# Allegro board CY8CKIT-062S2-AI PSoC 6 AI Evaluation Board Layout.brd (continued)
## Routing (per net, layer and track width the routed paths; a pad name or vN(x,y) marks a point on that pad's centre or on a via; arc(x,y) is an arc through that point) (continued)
VCC_3V3: length 116.3
  TOP w0.229: v1(29.54,39.71) 29.54,40.03 R81.1 ; v1(6.23,19.3) 6.23,19.35 6.09,19.5 C66.1 6.09,20.28 5.85,20.53 U3.8 ; U19.B2 U19.B3 17.89,21.54 17.05,21.54 C115.1 16.22,21.56 15.34,20.68 15.34,20.31 15.57,20.08 v1(15.57,18.62) ; U18.5 10.39,20.14 C116.2 v1(9.94,20.12) ; v1(16.47,13.86) C81.1 17.08,14.44 17.11,14.41 FB10.1 ; v1(5.18,40.07) 5.18,40.83 R73.1 ; R285.2 13.67,21.82 12.68,20.83 v1(12.68,20.3) 12.57,20.18 12.27,20.18 C121.1 12.21,20.8 12.15,20.85 U18.8 ; U3.6 7.15,20.58 7.35,20.37 7.35,19.87 C67.1 v1(7.34,19.32)
  L03_SIG1 w0.229: v1(7.44,44.53) 6.64,44.53 5.44,43.33 5.44,40.34 v1(5.18,40.07) 4.97,39.86 4.97,39.14 5.27,38.84 5.27,37.29 v1(5.44,37.11) ; v1(7.34,19.32) 7.34,20.67 8.14,21.46 v1(8.14,21.64)
  L04_SIG2 w0.229: v1(29.54,39.71) 29.62,39.64 29.62,39.07 29.11,38.56 28.3,38.56 28.02,38.84 26.76,38.84 26.44,38.52 26.44,37.52 26.21,37.29 25.51,37.29 24.98,37.82 19.02,37.82 v1(18.59,37.39) 17.2,37.39 16.2,38.39 6.04,38.39 5.67,38.02 5.67,37.34 v1(5.44,37.11) ; v1(13.38,43.59) 8.34,43.59 7.44,44.49 v1(7.44,44.53) ; v1(9.94,20.12) 10.37,20.55 12.01,20.55 12.26,20.3 v1(12.68,20.3) ; 7.34,19.26 7.34,19.26 6.96,18.89 6.62,18.89 6.23,19.27 v1(6.23,19.3) 4.53,19.3 v1(4.1,19.74) ; 7.34,19.26 8.1,18.51 15.41,18.51 15.52,18.62 v1(15.57,18.62) ; 7.34,19.26 v1(7.34,19.32)
  BOTTOM w0.229: TP10.1 R39.1 13.21,18.39 13.21,19.76 12.68,20.29 v1(12.68,20.3) ; U4.2 5.44,44.02 5.67,44.25 6.71,44.25 6.9,44.06 C68.1 v1(7.44,44.53) ; v1(5.44,37.11) 5.44,36.8 3.74,35.1 3.74,32.94 J17.5 3.03,29.85 3.03,27.06 3.54,26.54 3.54,20.29 v1(4.1,19.74) ; v1(18.59,37.39) 18.57,37.42 J16.2 ; U5.2 29.31,41.16 29.71,40.76 C71.1 29.5,40.1 29.5,39.76 v1(29.54,39.71) ; v1(13.38,43.59) J15.1 ; v1(8.14,21.64) 7.98,21.8 R286.2
  BOTTOM w0.381: v1(15.57,18.62) 15.57,17.58 15.34,17.35 13.46,17.35 13.18,17.63 R39.1
  vias: v1(18.73,14.3) v1(19.26,14.3)
VCC_3V6: length 9.4
  TOP w0.229: R26.1 v1(27.71,11.16)
  TOP w0.381: v1(29,32.14) 28.66,32.14 28.26,31.74 R96.1
  L03_SIG1 w0.229: v1(10.77,16.52) 10.77,16.49 11.52,15.75 11.69,15.75 12.04,15.4 12.89,15.4 12.9,15.41 v1(14.12,15.41)
  BOTTOM w0.229: v1(10.77,16.52) C253.1 11.1,15.89 11.38,15.61 11.38,14.57 11.27,14.46 R21.1 ; v1(23.96,12.55) 23.74,12.33 R25.1 ; R19.1 v1(20.63,12.74)
  vias: v1(14.12,14.83) v1(18.5,9.96) v1(18.48,9.37) v1(21.29,10.06) v1(21.29,9.53) v1(30.11,12.7) v1(30.59,12.37)
VCCD: length 17
  TOP w0.229: U1.A2 v1(6.79,26.08)
  L04_SIG2 w0.229: v1(4.84,24.46) 4.25,23.88 4.25,22.67 5.76,21.16 8.34,21.16 8.78,21.59 v1(12.84,21.59)
  BOTTOM w0.229: v1(12.84,21.59) 12.84,21 R40.2 12.71,20.73 12.5,20.73 12.48,20.71 TP12.1 ; v1(4.84,24.46) 5.29,24.92 5.29,25.44 5.58,25.73 6.09,25.73 6.29,25.93 C39.1 6.71,26.16 v1(6.79,26.08)
VDD_NS: length 3.5
  TOP w0.229: U1.J1 v1(12.64,25.43)
  BOTTOM w0.229: FB3.1 12.04,23.85 C36.1 12.27,24.08 C55.1 12.27,25.06 v1(12.64,25.43)
VDDA: length 7.6
  TOP w0.15: U1.A13 v1(6.79,33.88) ; U1.A12 v1(6.79,33.23)
  BOTTOM w0.229: FB5.1 5.39,29.58 5.39,30.86 5.62,31.09 5.82,31.09 C40.1 6.31,31.58 C48.1 C49.1 ; C49.1 6.65,33.08 v1(6.79,33.23) ; C49.1 C47.1 6.79,33.88 v1(6.79,33.88)
VDDA_RADAR: length 3.5
  TOP w0.229: FB7.2 23.88,21.37 C75.1 23.84,20.41 23.84,20.17 23.56,19.88 23.56,19.61 23.03,19.09 U6.J1
VDDD: length 84.4
  TOP w0.127: v1(29.65,23.95) 29.65,28.57 29.2,29.02 28.25,29.02 28.01,29.26 28.01,29.63 27.64,30 27.64,30.27 R41.1
  TOP w0.229: U1.K12 v1(13.29,33.23) ; v1(13.17,35.41) 7.4,35.41 6.49,36.32 5.18,36.32 3.85,34.98 3.85,30.41 3.65,30.21 3.65,28.93 3.85,28.73 3.85,28.72 5.11,27.46 5.11,25.86 v1(4.76,25.5) ; U1.A1 v1(6.79,25.43)
  L03_SIG1 w0.229: v1(13.62,34.44) 13.62,33.56 v1(13.29,33.23)
  L04_SIG2 w0.229: v1(4.76,25.5) 5.06,25.5 5.29,25.27 5.29,24.99 5.67,24.61 ; v1(29.65,23.95) 29.32,23.62 29.32,22.78 29.52,22.58 29.91,22.58 30.74,21.75 30.74,17.22 30.39,16.87 29.24,16.87 28.9,17.21 27.92,17.21 27.68,16.97 23.34,16.97 20.27,20.04 20.27,21.15 19.73,21.69 19.32,21.69 18.78,21.16 17.24,21.16 16.75,20.67 16.29,20.67 15.7,21.26 v1(14.31,21.26) 13.55,22.03 8.31,22.03 8.08,22.25 5.28,22.25 4.68,22.84 4.68,23.62 5.67,24.61 ; 5.67,24.61 v1(6.77,24.61)
  BOTTOM w0.229: C51.1 6.39,24.56 6.72,24.56 v1(6.77,24.61) ; C51.1 C50.1 6.62,25.26 v1(6.79,25.43) ; C51.1 6.29,24.13 6.83,23.58 C38.1 8.33,23.4 R284.1 8.4,23.08 8.54,22.94 9.41,22.94 9.81,22.53 9.81,21.74 FB4.1 ; v1(13.17,35.41) C52.1 13.17,34.44 v1(13.62,34.44) ; R275.1 14.87,22.28 14.87,21.65 14.47,21.26 v1(14.31,21.26)
VDDD_RADAR: length 3.9
  TOP w0.229: U6.H1 23.53,18.9 24.06,19.43 24.06,19.69 24.36,19.99 24.36,20 24.78,20.42 C73.1 24.78,20.81 FB6.2
VDDIO0: length 2.9
  TOP w0.229: U1.C4 v1(8.09,27.38)
  BOTTOM w0.229: R277.2 8.62,29.38 C54.1 C53.1 8.09,27.42 v1(8.09,27.38)
VDDIO2: length 3
  TOP w0.229: U1.L4 v1(13.94,27.38)
  BOTTOM w0.229: R278.2 14.05,29.18 13.85,29.18 C46.1 C45.1 13.43,27.92 13.78,27.58 13.78,27.54 v1(13.94,27.38)
VDDIO_1YN: length 35.1
  TOP w0.229: R44.1 R45.1 19.42,30.01 19.23,30.2 18.96,30.2 18.82,30.33 R58.1 18.41,30.67 18.29,30.54 R47.1 ; R44.1 19.59,29.11 20.26,29.11 20.48,28.88 20.5,28.88 v1(20.59,28.79) ; R44.1 R43.1 R50.1 19.42,27.18 20.03,26.57 R42.1 R46.1 ; C99.1 23.64,37.04 U17.36 ; C99.1 24.62,38.02 24.62,38.35 24.77,38.51 v1(25.36,38.51) 25.89,38.51 26.39,39 26.39,39.51 R97.2 ; C99.1 24.19,38.01 24.19,38.53 C249.1 24.75,39.75 Y3.P
  L03_SIG1 w0.229: v1(20.59,28.79) 20.59,28.51 20.82,28.28 21.54,28.28 22.15,28.89 22.15,31.43 21.23,32.35 21.23,33.01 21.98,33.76 22.38,33.76 24.22,35.6 v1(24.22,37.01)
  BOTTOM w0.229: v1(24.22,37.01) 24.22,38.1 24.62,38.51 v1(25.36,38.51) 26.01,38.51 26.57,39.07 26.63,39.08 27.95,39.08 28.01,39.07 28.57,38.51 28.86,38.51 TP24.1
VDDLF_RADAR: length 4.8
  TOP w0.178: U6.M3 21.46,17.32 21.35,17.32 21.28,17.25 20.02,17.25 C82.1
  TOP w0.229: FB10.2 17.97,15.7 17.97,16 18.2,16.23 18.37,16.23 18.8,16.66 19.44,16.66 C82.1
VDDPLL_RADAR: length 6
  TOP w0.178: U6.M4 21.45,16.81 20.86,16.81 19.47,15.42 C79.1
  TOP w0.229: C79.1 19.21,15.42 19.09,15.3 18.77,15.3 18.3,14.84 18.3,13.79 17.69,13.18 FB9.2
VDDRF_RADAR: length 24
  TOP w0.178: C84.1 19.06,18.42 19.34,18.13 20.88,18.13 21.14,18.39 U6.M1
  TOP w0.229: v1(23.49,12.76) 23.06,12.76 22.91,12.61 C83.1 ; 24.07,12.03 C85.1 23.6,12.03 23.37,11.8 C83.1 ; 24.07,12.03 C86.1 24.85,12.15 24.85,12.88 24.53,13.2 U6.F9 ; 24.07,12.03 24.39,12.35 24.39,12.78 24.13,13.04 24.13,13.93 24.03,14.03 U6.G9 ; C84.1 19.06,18.9 18.78,19.18 v1(18.04,19.18) ; C83.1 22.89,11.78 FB11.2
  L03_SIG1 w0.229: v1(18.04,19.18) 18.58,19.18 20.23,17.53 20.23,14.83 20.56,14.5 22.11,14.5 23.05,13.56 23.05,13.15 23.44,12.76 v1(23.49,12.76)
VDDUSB: length 2.8
  TOP w0.15: U1.M1 v1(14.59,25.43)
  BOTTOM w0.229: v1(14.59,25.43) 14.86,25.16 C41.1 14.86,24.47 14.86,24.47 C42.1 14.86,23.35 R275.2
VDDVCO_RADAR: length 7
  TOP w0.229: FB8.2 19.87,11.2 19.87,11.8 19.66,12.01 19.42,12.01 C77.1 19.39,12.55 20.15,13.31 20.15,14.15 20.33,14.33 20.33,14.99 21.23,15.89 U6.M6
VIN: length 6.3
  BOTTOM w0.229: R20.1 R22.1 9.37,10.73 9.61,10.97 ; TP33.1 16.7,6.78 15.79,7.7 15.26,7.7 14.05,8.92 v1(13.85,8.92)
  vias: v1(10.19,11.71) v1(10.19,11.15) v1(13.85,9.45)
ANT0: length 2.1
  TOP w0.18: U17.41 21.39,38.3 C255.2
ANT1: length 2.3
  TOP w0.18: C254.2 21.39,40.47 C250.1 21.38,41.52 C246.1
ANT2: length 5.2
  TOP w0.18: J5.S 17.13,40.6 arc(17.29,39.79) 17.75,39.1 arc(18.63,38.51) 19.67,38.3 C255.1
BT_DEV_WAKE: length 15.2
  TOP w0.15: U17.39 22.29,36.74 22.3,36.74 v1(22.3,36.78) ; U1.N6 15.37,29 15.71,29.34 15.71,29.64 16.17,30.1 16.17,30.87 17.46,32.16 17.46,33.68 17.87,34.09 17.87,35.2 17.28,35.79 v1(17.28,36.68)
  L04_SIG2 w0.157: v1(17.28,36.68) 19.69,36.68 19.94,36.42 21.94,36.42 v1(22.3,36.78)
BT_HOST_WAKE: length 17.3
  TOP w0.15: U17.38 22.74,36.71 v1(22.82,36.78) ; U1.L7 v1(13.3,29.97)
  L03_SIG1 w0.157: v1(18.48,31.89) 18.48,32.66 18.53,32.72 18.53,34.05 17.81,34.76 v1(17.81,36.09)
  L04_SIG2 w0.157: v1(22.82,36.78) 22.74,36.71 22.74,36.4 22.44,36.09 v1(17.81,36.09)
  BOTTOM w0.15: v1(13.3,29.97) 13.52,30.2 15.45,30.2 15.71,30.45 15.71,30.81 16.85,31.95 18.4,31.95 18.47,31.89 v1(18.48,31.89)
BT_REG_ON: length 14.9
  TOP w0.15: U17.14 21.84,29.81 v1(21.68,29.64) ; U1.M6 v1(14.59,28.68) ; R58.2 19.45,30.67 v1(19.82,30.3)
  L03_SIG1 w0.157: v1(19.82,30.3) 19.44,30.68 19.44,31.14 20.28,31.98 20.96,31.98 21.68,31.27 v1(21.68,29.64)
  BOTTOM w0.15: v1(21.68,29.64) 21.29,29.64 21.12,29.46 19.46,29.46 18.56,28.56 18.22,28.56 18.1,28.68 v1(14.59,28.68)
BT_UART_CTS: length 1.5
  TOP w0.15: U17.4 20.22,34.19 20.01,34.41 R59.1
BT_UART_RTS: length 1.5
  TOP w0.15: R60.1 19.93,33.41 20.27,33.74 U17.5
BT_UART_RXD: length 2.3
  TOP w0.15: R57.1 19.53,36.3 19.92,35.92 19.92,35.44 20.27,35.09 U17.2
BT_UART_TXD: length 1.8
  TOP w0.15: U17.3 20.23,34.64 19.53,35.34 R56.1
ECO_XTAL_IN_P12_6: length 7.8
  TOP w0.15: U1.A4 v1(6.79,27.38)
  L03_SIG1 w0.089: v1(9.31,31.24) 9.03,31.24 8.81,31.03 8.81,29.68 8.19,29.06 7.35,29.06 7.12,28.82 7.12,27.7 v1(6.79,27.38)
  BOTTOM w0.089: Y2.1 10.71,31.47 C62.1 9.56,31.24 v1(9.31,31.24)
ECO_XTAL_OUT_P12_7: length 9.2
  TOP w0.15: U1.B4 v1(7.44,27.38)
  L03_SIG1 w0.089: v1(10.14,30.48) 9.41,30.48 9,30.07 9,29.59 8.42,29.01 8.42,28.54 8.23,28.35 7.86,28.35 7.77,28.26 7.77,27.7 v1(7.44,27.38)
  BOTTOM w0.089: v1(10.14,30.48) 9.97,30.31 9.79,30.31 C63.1 9.69,30.2 9.97,29.92 12.21,29.92 12.3,30.01 Y2.3
EXT_LPO: length 1.4
  TOP w0.15: R100.2 23.2,37.47 23.2,36.62 23.19,36.62 U17.37
I2C_SCL_P0_2: length 59.4
  TOP w0.15: 9.66,25.05 9.66,25.58 9.72,25.64 U1.E1 ; 9.66,25.05 9.82,24.89 10.76,24.89 11.03,24.62 11.03,24.03 10.89,23.89 U18.13 ; 9.66,25.05 9.39,24.78 9.39,24.13 9.19,23.93 8.12,23.93 7.76,23.57 R64.2 7.76,23.22 v1(7.4,22.86) ; R296.2 18.52,19.75 18.34,19.57 17.75,19.57 v1(17.68,19.64) 17.49,19.44 16.61,19.44 16.31,19.75 R282.1 ; v1(18.11,20.73) 17.92,20.92 U19.A3
  L03_SIG1 w0.157: v1(17.68,19.64) 17.68,20.29 v1(18.11,20.73) 18.14,20.75 18.14,21.18 19.47,22.52 19.47,26.95 18.86,27.56 18.86,29.52 18.66,29.71 18.66,31.47 18.86,31.66 18.86,36.18 v1(19.91,37.23)
  L04_SIG2 w0.157: J17.4 3.77,26.57 3.77,22.56 v1(4.71,21.62) 4.51,21.41 4.51,20.75 5.53,19.73 9.15,19.73 9.52,19.36 10.33,19.36 10.72,18.97 12.29,18.97 12.32,18.94 14.83,18.94 14.9,19.02 15.4,19.02 15.99,19.61 17.65,19.61 17.68,19.64 v1(17.68,19.64)
  BOTTOM w0.15: v1(4.71,21.62) 4.98,21.88 5.59,21.88 6.56,22.86 v1(7.4,22.86) ; J16.4 20.57,37.88 v1(19.91,37.23)
I2C_SDA_P0_3: length 59.7
  TOP w0.089: 9.25,25.15 9.36,25.25 9.36,25.71 9.38,25.73 9.38,26.49 9.59,26.7 10.02,26.7 U1.F3
  TOP w0.15: 7.07,23.95 4.99,23.95 4.77,23.74 ; 7.07,23.95 7.07,23.38 R65.2 ; 7.07,23.95 7.37,24.26 7.37,24.26 7.4,24.28 7.76,24.28 7.78,24.31 v1(7.8,24.31) 7.81,24.31 7.83,24.33 8.82,24.33 8.98,24.49 8.98,24.87 9.25,25.15 ; J17.3 4.06,23.74 4.77,23.74 ; 4.77,23.74 4.77,22.24 5.24,21.77 5.24,21.56 4.96,21.29 v1(4.96,20.85) ; U19.A2 18.32,21.15 18.54,20.93 18.54,20.6 18.41,20.47 18.41,20.29 v1(18.08,19.96) 18.04,19.96 17.95,20.05 17.55,20.05 17.3,19.8 17.1,19.8 R281.1 ; v1(10.14,24.26) 10.39,24.01 U18.14
  L03_SIG1 w0.157: v1(18.08,19.96) 18.62,20.49 18.62,21.22 19.72,22.33 19.72,27.1 19.13,27.69 19.13,29.61 18.92,29.82 18.92,31.36 19.13,31.57 19.13,35.64 v1(20.32,36.83)
  L04_SIG2 w0.157: v1(4.96,20.85) 5.79,20.03 9.29,20.03 9.65,19.67 10.08,19.67 10.52,20.12 11.72,20.12 12,19.84 12,19.63 12.43,19.2 14.68,19.2 14.75,19.27 15.29,19.27 15.88,19.87 17.3,19.87 17.47,20.04 17.96,20.04 18.04,19.96 v1(18.08,19.96) ; v1(10.14,24.26) 7.85,24.26 v1(7.8,24.31)
  BOTTOM w0.15: v1(20.32,36.83) 19.63,36.83 19.39,37.07 19.39,39.61 J16.3 ; R295.2 17.25,20.04 17.96,20.04 18.04,19.96 v1(18.08,19.96)
IMU_INT1_P1_5: length 8.8
  TOP w0.15: U18.4 9.41,21.41 9.23,21.23 v1(9.23,20.93) ; U1.J3 v1(12.64,26.73)
  L03_SIG1 w0.157: v1(9.23,20.93) 9.31,20.93 10.47,22.1 10.48,22.1 10.71,22.32 10.71,22.33 12.79,24.41 12.79,25.07 13,25.28 13,26.37 v1(12.64,26.73)
IMU_INT2_P0_4: length 9.3
  TOP w0.15: U18.9 10.89,21.91 v1(10.32,22.48) ; U1.F2 v1(10.69,26.08)
  L03_SIG1 w0.157: v1(10.69,26.08) 10.69,26.41 10.85,26.57 12.1,26.57 12.26,26.41 12.26,24.42 v1(10.32,22.48)
KP_UART_RX_P5_1: length 46.3
  TOP w0.15: R289.1 15.03,39.42 15.96,39.42 16.39,38.99 16.39,37.64 v1(16.59,37.44)
  L03_SIG1 w0.157: v1(26.88,12.98) 27.27,12.98 27.44,13.15 27.44,13.72 26.41,14.74 26.41,20.43 26.65,20.67 26.65,23.66 26.53,23.79 26.53,25.5 27.57,26.54 27.57,27.15 27.14,27.58 27.14,30.95 26.77,31.32 26.77,33.97 26.12,34.62 v1(26.12,36.14)
  BOTTOM w0.089: v1(26.88,12.98) 27.23,12.98 27.36,13.11 27.36,14.16 26.38,15.13 26.38,15.84 26.29,15.93 26.13,15.93 R34.1
  BOTTOM w0.15: R34.1 26.06,16.33 25.91,16.48 25.49,16.48 24.85,17.12 U2.21 ; v1(26.12,36.14) 26.12,36.25 25.77,36.6 25.45,36.6 24.8,35.94 21.9,35.94 21.4,36.45 19.56,36.45 19.18,36.83 17.87,36.83 17.58,37.12 16.92,37.12 v1(16.59,37.44)
KP_UART_TX_P5_0: length 49.5
  TOP w0.15: R288.1 15.71,38.86 15.96,38.86 16.11,38.71 16.11,37.82 16.04,37.74 v1(16.04,37.39)
  L03_SIG1 w0.157: v1(28.36,35.99) 28.36,33.15 27.95,32.74 27.95,31.5 27.54,31.09 27.54,27.71 27.83,27.43 27.83,26.35 26.79,25.31 26.79,23.89 26.98,23.7 26.98,20.64 26.67,20.33 26.67,15.02 27.85,13.84 27.85,12.95 v1(27.14,12.24)
  L04_SIG2 w0.157: v1(16.04,37.39) 16.11,37.31 v1(16.11,36.35)
  BOTTOM w0.102: v1(27.14,12.24) 27.59,12.7 27.59,14.2 26.63,15.17 26.63,16.28 26.12,16.79 25.64,16.79 25.25,17.18 U2.20
  BOTTOM w0.15: v1(16.11,36.35) 16.37,36.09 17.26,36.09 17.74,36.58 19.08,36.58 19.46,36.2 21.14,36.2 21.73,35.61 24.93,35.61 25.08,35.46 25.08,35.33 25.39,35.02 25.89,35.02 26.12,35.26 26.12,35.48 26.3,35.66 28.03,35.66 v1(28.36,35.99)
KP_USB_DM: length 18.3
  TOP w0.114: J1.A7 25.29,6.26 25.15,6.13 25.15,5.65 v1(25.39,5.42) ; J1.B7 v1(24.29,7.59)
  L03_SIG1 w0.114: 24.8,7.59 24.91,7.71 24.91,8.3 25.89,9.29 25.89,12.88 v1(25.65,13.12) ; 24.8,7.59 v1(24.29,7.59) ; 24.8,7.59 24.92,7.47 24.92,6.96 24.03,6.07 24.03,5.11 24.48,4.66 24.9,4.66 25.16,4.92 25.16,5.19 v1(25.39,5.42)
  BOTTOM w0.114: v1(24.29,7.59) 24.81,7.59 24.93,7.48 24.93,7.33 U16.1 ; v1(25.65,13.12) 25.89,13.35 25.89,14.15 25.42,14.62 24.97,14.62 24.73,14.87 24.73,15.18 24.51,15.39 R37.1
KP_USB_DP: length 18.3
  TOP w0.114: J1.A6 24.79,6.25 24.92,6.12 24.92,5.65 v1(24.68,5.42) ; J1.B6 v1(25.79,7.59)
  L03_SIG1 w0.114: 25.28,7.59 25.17,7.49 25.17,6.86 25,6.69 25,6.55 25.24,6.31 25.24,6.17 25.14,6.07 25,6.07 24.76,6.3 24.62,6.3 24.28,5.97 24.28,5.21 24.58,4.91 24.8,4.91 24.91,5.03 24.91,5.19 v1(24.68,5.42) ; 25.28,7.59 v1(25.79,7.59) ; 25.28,7.59 25.16,7.71 25.16,8.2 26.15,9.18 26.15,12.9 v1(26.36,13.12)
  BOTTOM w0.114: U16.2 25.16,7.34 25.16,7.48 25.27,7.59 v1(25.79,7.59) ; R35.1 25.21,15.39 24.95,15.14 24.95,14.97 25.07,14.85 25.52,14.85 26.12,14.25 26.12,13.35 v1(26.36,13.12)
KP_VBUS: length 1.8
  TOP w0.229: R101.1 3.1,5.25 v1(2.99,5.13)
  BOTTOM w0.229: v1(22.92,4.72) 22.93,4.73 v1(23.5,4.73)
  BOTTOM w0.254: v1(23.5,4.73) D10.K
  vias: v1(2.98,6.3) v1(22.41,8.1) v1(23,8.1) v1(26.96,8.13) v1(27.52,8.13)
LBCPP_CE_N_P5_7: length 39
  TOP w0.15: U1.N10 v1(15.24,31.93)
  L03_SIG1 w0.089: 17.45,23.02 17.5,23.02 17.8,22.72 17.8,22.32
  L03_SIG1 w0.157: 17.45,23.02 17.2,23.27 17.2,24.68 17.83,25.31 v1(17.83,26.64) ; v1(16.8,16.05) 18.25,16.05 18.81,16.61 18.81,17.35 17.25,18.91 17.25,20.42 17.8,20.98 17.8,22.32
  L04_SIG2 w0.157: v1(16.8,16.05) 15,16.05 14.54,16.51 14.54,16.79 14.26,17.07 10.61,17.07 10.16,17.52 9.84,17.52 9.25,18.11 7.91,18.11 7.55,18.47 7.25,18.47 7.24,18.47 6.95,18.47 6.94,18.47 5.26,18.47 3.91,17.12 3.91,15.84 v1(3.49,15.42) ; v1(15.24,31.93) 15.25,31.93 16.11,31.07 16.11,28.7 17.83,26.97 v1(17.83,26.64)
  BOTTOM w0.15: v1(3.49,15.42) 3.69,15.22 R10.2 4.38,14.86 4.6,14.63 4.6,14.31 U8.4
LBCPP_CHG_N_P5_6: length 19.5
  TOP w0.15: v1(12.53,16.26) 12.53,15.61 R298.1 ; U1.N9 v1(15.24,31.28)
  L03_SIG1 w0.157: v1(17.37,26.85) 17.37,26.2 17.36,26.19 17.36,26.18 16.98,25.8 16.98,25.26 16.61,24.89 16.61,23.09 16.84,22.86 16.84,22.12 14.57,19.84 14.57,19.5 13.95,18.88 13.95,17.67 12.91,16.64 12.91,16.64 12.53,16.26 v1(12.53,16.26)
  L04_SIG2 w0.157: v1(15.24,31.28) 15.71,30.81 15.71,28.73 17.37,27.07 v1(17.37,26.85)
LBCPP_EN1_P6_1: length 24.8
  TOP w0.15: U1.L10 v1(13.94,31.93)
  L03_SIG1 w0.157: v1(13.94,31.93) 13.94,31.79 13.33,31.18 13.33,30.51 12.94,30.12 12.94,29.9 12.66,29.62 10.04,29.62 9.61,29.18 9.61,28.07 9.97,27.71 9.97,26.99 9.39,26.42 9.39,24.95 9.09,24.65 9.09,24.02 5.86,20.79 5.86,20.21 5.06,19.41 5.06,15.61 v1(4.93,15.48)
  BOTTOM w0.15: U8.6 5.75,15.37 6.04,15.66 R11.2 R3.1 5.24,15.78 v1(4.93,15.48)
LBCPP_EN2_P6_0: length 28.3
  TOP w0.15: U1.M10 v1(14.59,31.93)
  L03_SIG1 w0.157: v1(3.16,15.88) 3.71,15.88 4.5,15.09 5.09,15.09 5.45,15.45 5.45,19.23 6.31,20.09 6.31,20.78 9.35,23.82 9.35,24.54 9.66,24.85 9.66,26.23 10.3,26.87 10.3,27.84 9.97,28.17 9.97,29.05 10.2,29.29 13.11,29.29 13.65,29.83 13.65,30.41 13.58,30.48 13.58,30.87 14.59,31.88 v1(14.59,31.93)
  BOTTOM w0.15: U8.5 4.86,14.96 4.44,15.38 R4.1 R12.2 v1(3.16,15.88)
LBCPP_ITERM_P6_3: length 44.7
  TOP w0.15: U1.M11 v1(14.59,32.58)
  L03_SIG1 w0.089: v1(15.76,32.01) 15.75,32.01 15.18,32.58 v1(14.59,32.58)
  L03_SIG1 w0.157: v1(9.97,17.14) 10.29,16.82 10.29,15.04 11.34,13.99 12.07,13.99 12.53,14.45 14.4,14.45 14.59,14.64 14.59,16.94 14.77,17.12 14.77,18.58 15.36,19.17 15.36,19.46 17.12,21.22 17.12,22.98 16.92,23.18 16.92,24.83 17.42,25.33 v1(17.42,25.68) ; v1(4.15,8.53) 4.15,10.92 6.05,12.82 6.05,14.15 7.1,15.2 v1(7.1,18.11)
  L04_SIG2 w0.157: v1(17.42,25.68) 18.21,26.48 18.21,26.96 16.37,28.8 16.37,31.39 15.76,32 v1(15.76,32.01)
  BOTTOM w0.15: v1(7.1,18.11) 8.48,18.11 9.45,17.14 v1(9.97,17.14) ; R283.2 3.82,9.67 4.15,9.35 v1(4.15,8.53)
LBCPP_PG_N_P5_5: length 21.6
  TOP w0.15: U1.M9 v1(14.59,31.28) ; R297.1 13.53,15.39 13.07,15.85 v1(13.07,16.25)
  L03_SIG1 w0.089: v1(14.59,31.28) U1.M9 14.27,29.71 13.37,28.81 13.37,27.49 13.81,27.05 14.64,27.05
  L03_SIG1 w0.157: v1(13.07,16.25) 13.07,16.25 12.69,15.87 12.23,15.87 12.07,16.03 12.07,16.51 13.29,17.73 13.29,19.41 15.75,21.86 15.75,22.76 15.85,22.86 15.85,25.85 14.64,27.05
MAG_INT_P1_0: length 22.7
  TOP w0.15: v1(12.61,19.66) 11.85,18.9 8.41,18.9 v1(7.98,19.33) ; U1.G2 v1(11.34,26.08) ; v1(19.6,21.18) 19.59,21.18 19.59,21.17 U19.A1
  L03_SIG1 w0.157: v1(7.98,19.33) 8.49,19.83 8.49,20.75 9.86,22.12 9.86,22.56 11.9,24.6 11.9,25.53 11.35,26.08 v1(11.34,26.08)
  L04_SIG2 w0.089: 16.23,20.27 16.09,20.13 15.25,20.13 15.24,20.14
  L04_SIG2 w0.157: 16.23,20.27 17.04,20.27 17.14,20.37 18.79,20.37 19.45,21.03 19.45,21.03 v1(19.6,21.18) ; 15.24,20.14 13.94,20.14 13.46,19.66 v1(12.61,19.66)
P5LP1_2: length 14.1
  BOTTOM w0.15: SW3.2 25.86,11.86 27.29,11.86 27.81,12.38 SW3.1 29.13,12.38 29.55,12.8 29.55,16.56 29.22,16.89 29.22,18.16 28.91,18.47 28.18,18.47 27.92,18.72 27.92,19.68 27.5,20.11 U2.13
P5LP1_4: length 17.8
  TOP w0.15: R38.2 v1(31.02,6.12)
  L03_SIG1 w0.157: v1(29.7,17.68) 29.97,17.41 29.97,13.15 29.35,12.52 29.35,10.49 29.88,9.96 30.79,9.96 31.53,9.22 31.53,8.33 31.02,7.82 v1(31.02,6.12)
  L04_SIG2 w0.157: v1(29.7,17.68) 29.12,18.26 28.2,18.26 v1(27.54,18.92)
  BOTTOM w0.15: U2.15 27.36,19.31 27.54,19.13 v1(27.54,18.92)
P5LP_SIO_VREF: length 2.8
  BOTTOM w0.15: R29.2 R28.2 18.06,24.35 18.3,24.11 18.3,23.95 18.54,23.71 U2.48
P5LP_SWCLK: length 2.9
  BOTTOM w0.15: TP8.1 28.63,19.25 28.63,20.14 28.26,20.51 U2.12
P5LP_SWDIO: length 2
  BOTTOM w0.15: U2.11 27.59,20.91 28.01,21.32 TP9.1
P5LP_VCCD: length 19.4
  L03_SIG1 w0.229: v1(20.96,14.96) 20.96,20.48 22.02,21.54 22.02,25.24 v1(20.84,26.43)
  BOTTOM w0.15: v1(20.96,14.96) 21.78,14.96 22.43,15.61 C25.1 22.43,16.77 22.85,17.18 U2.26
  BOTTOM w0.229: U2.57 21.65,26.74 21.7,26.8 C26.1 21.11,27.16 20.84,26.89 v1(20.84,26.43)
P5LP_VDD: length 72.9
  TOP w0.229: R27.1 28.38,9.4 28.88,9.4 v1(29.01,9.53)
  L03_SIG1 w0.229: v1(28.23,26.35) 28.23,25.42 27.46,24.65 27.43,24.65 27.18,24.41 27.18,24.06 28.09,23.15 28.09,18.52 28.23,18.38 v1(28.23,16.64) 28.23,16.48 27.59,15.85 v1(27.59,14.88) 27.59,14.66 28.24,14.01 28.24,10.82 29.01,10.06 v1(29.01,9.53)
  L04_SIG2 w0.229: v1(27.59,14.88) 25.61,14.88 25.02,14.3 ; v1(19.9,28.68) 20.05,28.53 20.25,28.53 20.49,28.28 21.43,28.28 21.9,28.75 v1(23.17,28.75) 23.27,28.65 25.61,28.65 v1(25.78,28.47) 26.1,28.47 v1(28.23,26.35) ; 25.02,14.3 21.41,17.91 18.2,17.91 17.46,18.65 v1(16.14,18.65) ; 25.02,14.3 v1(25.02,13.92)
  BOTTOM w0.15: v1(28.23,16.64) C22.1 C23.1 28.12,17.88 27.03,17.88 26.8,18.12 U2.17 ; v1(25.02,13.92) 24.7,13.92 23.7,14.91 C16.1 C17.1 23.65,16.3 U2.24 ; v1(25.78,28.47) C27.1 25.79,27.95 C28.1 25.65,27 U2.67 ; U2.35 18.57,18.51 18.35,18.29 17.78,18.29 C19.1 C18.1 v1(16.14,18.65) ; v1(28.23,26.35) 28.63,25.94 TP5.1 ; C20.1 16.42,22.11 C21.1 17.93,22.11 17.93,22.11 U2.44 ; U2.52 19.65,26.53 19.09,27.09 19.09,27.27 C30.1 ; v1(27.59,14.88) 27.09,15.39 R33.1 ; 22.98,27.98 C31.1
  BOTTOM w0.229: U2.59 22.45,26.35 22.98,26.88 C32.1 22.98,27.98 ; C20.1 16.39,22.08 16.15,22.08 16.08,22.01 16.08,22.01 16,21.92 16,20.93 16.18,20.75 16.18,20.26 15.63,19.71 15.63,19.16 v1(16.14,18.65) ; v1(19.9,28.68) 19.25,28.68 19.01,28.44 19.01,28.15 C29.1 C30.1 ; v1(23.17,28.75) 22.98,28.56 C31.1
P5LP_XRES: length 3.2
  BOTTOM w0.15: U2.10 27.44,21.31 28.63,22.5 TP7.1
P6_RESET_L: length 65.6
  TOP w0.15: R41.2 26.68,29.85 C57.1 26.7,28.08 SW1.2 SW1.1 26.72,24.38 26.87,24.23 v1(27.61,24.23) ; J4.10 v1(7.42,36.96) ; U1.F1 v1(10.04,25.43)
  L03_SIG1 w0.157: v1(9.84,23.5) 9.74,23.6 9.74,24.38 10.04,24.69 v1(10.04,25.43) ; v1(27.61,24.23) 27.97,24.23 28.51,23.7 28.51,18.97 29.27,18.21 v1(29.73,18.21) ; v1(5.39,22.81) 5.65,23.06 5.65,24.15 5.12,24.68 5.12,25.71 4.96,25.87 v1(4.96,28.41)
  L04_SIG2 w0.157: v1(5.39,22.81) 6.51,22.81 6.97,23.27 9.23,23.27 9.46,23.5 v1(9.84,23.5) 10.88,22.45 14.45,22.45 15.12,21.79 17.42,21.79 17.63,21.58 18.61,21.58 19.16,22.12 20.05,22.12 20.64,21.54 20.64,21.37 21.11,20.9 21.11,19.99 23.33,17.78 28.99,17.78 29.48,17.29 29.86,17.29 30.09,17.52 30.09,17.85 v1(29.73,18.21)
  BOTTOM w0.15: v1(27.61,24.23) 27.48,24.11 U2.3 ; v1(7.42,36.96) 6.96,36.96 4.61,34.6 4.61,32.54 4.33,32.26 4.33,30.84 4.96,30.2 v1(4.96,28.41)
P6_SWCLK_P6_7: length 24.4
  TOP w0.15: J4.4 11.23,37.14 11.41,36.96 12.58,36.96 v1(14.06,35.48) 14.36,35.18 14.36,34.24 14.27,34.15 U1.M13
  L03_SIG1 w0.157: v1(17.05,35.28) 17.05,35.04 16.97,34.96 16.97,34.64 17.38,34.23 17.38,32.89 17.69,32.59 17.69,27.36 18.26,26.78 18.26,25.43 18.72,24.97 18.72,23.67 v1(18.14,23.09)
  L04_SIG2 w0.157: v1(14.06,35.48) 14.41,35.13 16.9,35.13 v1(17.05,35.28)
  BOTTOM w0.15: U2.47 18.37,23.31 v1(18.14,23.09)
P6_SWDIO_P6_6: length 23.6
  TOP w0.15: U1.N12 14.62,33.2 14.62,33.83 14.84,34.06 v1(14.84,34.75) 14.84,35.25 12.5,37.6 J4.2
  L03_SIG1 w0.157: v1(18.19,22.58) 18.26,22.58 18.98,23.3 18.98,25.08 18.54,25.52 18.54,26.93 17.97,27.51 17.97,32.72 17.66,33.02 17.66,34.49 v1(17.36,34.8)
  L04_SIG2 w0.157: v1(17.36,34.8) 17.31,34.75 v1(14.84,34.75)
  BOTTOM w0.15: v1(18.19,22.58) 18.2,22.58 18.53,22.91 U2.46
P6_SWO_P6_4: length 13.5
  TOP w0.15: U1.N11 15.25,32.58 15.25,35.2 13.14,37.31 13.14,40.16 12.96,40.34 10.6,40.34 9.96,39.69 J4.6
P6_TDI_P6_5: length 9.8
  TOP w0.15: J4.8 8.69,37.63 9.06,37.25 9.32,37.25 9.51,37.06 10.83,37.06 11.29,36.6 12.58,36.6 13.61,35.57 13.61,35.09 14.08,34.62 14.08,34.36 13.97,34.25 13.97,33.2 U1.M12
P6_USB_DM: length 33.5
  TOP w0.114: J2.B7 v1(8.97,7.58) ; v1(10.07,5.42) 9.84,5.65 9.84,6.13 9.97,6.27 J2.A7 ; U1.L1 v1(13.94,25.43)
  L03_SIG1 w0.114: v1(13.94,25.43) 14.32,25.81 14.77,25.81 14.95,25.62 14.95,25.28 14.81,25.14 14.81,24.8 14.95,24.66 14.95,23.38 14.71,23.14 14.51,23.14 14.27,22.89 14.27,22.7 13.8,22.22 11.21,22.22 8.99,20.01 8.99,10.96 9.6,10.35 9.6,7.69 9.49,7.58 ; v1(10.07,5.42) 9.85,5.19 9.85,4.9 9.55,4.6 9.08,4.6 8.69,4.99 8.69,6.02 9.6,6.94 9.6,7.46 9.49,7.58 ; v1(8.97,7.58) 9.49,7.58
  BOTTOM w0.114: U9.1 9.36,7.03 9.62,7.29 9.62,7.45 9.49,7.58 v1(8.97,7.58)
P6_USB_DP: length 33.4
  TOP w0.114: J2.A6 9.47,6.25 9.61,6.12 9.61,5.65 v1(9.37,5.42) ; U1.L2 v1(13.94,26.08) ; J2.B6 v1(10.47,7.58)
  L03_SIG1 w0.114: 9.97,7.58 v1(10.47,7.58) ; 9.97,7.58 9.85,7.46 9.85,6.83 9.68,6.65 9.68,6.51 9.9,6.29 9.9,6.14 9.8,6.04 9.66,6.04 9.43,6.27 9.29,6.27 8.94,5.92 8.94,5.09 9.18,4.85 9.44,4.85 9.59,5 9.59,5.19 v1(9.37,5.42) ; 9.97,7.58 9.85,7.69 9.85,10.45 9.25,11.06 9.25,19.9 11.31,21.97 13.9,21.97 15.2,23.27 15.2,25.74 14.87,26.08 v1(13.94,26.08)
  BOTTOM w0.114: U9.2 10.06,7.03 9.85,7.24 9.85,7.48 9.95,7.58 v1(10.47,7.58)
P6_USB_S_P6_2: length 33.9
  TOP w0.15: U1.L11 v1(13.94,32.58)
  L03_SIG1 w0.157: v1(13.94,32.58) 13.33,32.58 12.84,32.08 12.84,31.65 13.07,31.42 13.07,30.71 12.61,30.25 12.61,30 12.51,29.9 9.86,29.9 9.28,29.31 9.28,27.66 9.13,27.51 9.13,25.05 8.83,24.76 8.83,24.22 7.86,23.24 7.12,23.24 5.11,21.23 4.66,21.23 3.18,19.76 3.18,18.44 2.76,18.01 2.76,15.57 3.74,14.58 5.22,14.58 5.93,15.29 5.93,17.25 v1(5.95,17.27)
  BOTTOM w0.15: v1(5.95,17.27) 5.98,17.3 6.71,17.3 7,17.01 R280.2 7.34,16.47 7.49,16.32 7.49,16.08 7.69,15.87 R279.2
P6_VBUS: length 12.6
  TOP w0.229: 3.04,7.06 3.08,7.1 R102.1
  TOP w0.254: v1(2.4,7.06) 3.04,7.06
  L03_SIG1 w0.229: v1(7.68,8.13) 7.78,8.23 7.78,10.16 7.35,10.59 7.35,14.39 8,15.04 v1(8,17.1)
  BOTTOM w0.229: R279.1 8,16.48 v1(8,17.1) ; 8.33,4.75 8.33,4.75 v1(7.6,4.75)
  BOTTOM w0.254: v1(8.14,4.75) D4.K
  vias: v1(1.69,7.06) v1(7.12,8.13) v1(11.64,8.26) v1(12.23,8.26)
P6_VTARG: length 81.8
  TOP w0.229: R281.2 R282.2 15.93,20.35 15.78,20.49 v1(15.76,20.49) ; J4.1 12.5,41.22 12.27,41 9.33,41 8.75,40.41 v1(7.02,40.41)
  L03_SIG1 w0.229: v1(15.76,20.49) 15.78,20.49 14.96,19.68 14.96,19.34 14.37,18.74 14.37,17.33 v1(13.57,16.54)
  L04_SIG2 w0.229: v1(13.57,16.54) 13.57,16.26 13.9,15.93 14.56,15.93 14.94,15.54 17.05,15.54 17.23,15.72 v1(18.81,15.72) 18.85,15.72 19,15.57 23.04,15.57 24.36,14.26 24.36,13.92 24.82,13.45 25.15,13.45 25.21,13.51 25.79,13.51 26.14,13.86 26.14,14 26.37,14.23 26.69,14.23 27.01,13.92 v1(27.01,13.49) ; v1(15.76,20.49) 15.69,20.49 15.58,20.6 13.83,20.6 13.44,20.98 9.89,20.98 9.43,20.52 v1(8.85,20.52)
  BOTTOM w0.15: v1(18.81,15.72) 18.81,15.73 R30.1 ; v1(27.01,13.49) 27.01,14.05 26.06,15 R34.2
  BOTTOM w0.229: 8.47,20.9 v1(8.85,20.52) 8.86,20.51 9.75,20.51 11.02,21.78 FB3.2 ; 8.47,20.9 5.83,20.9 5.32,20.4 4.51,20.4 3.97,20.93 3.97,27.59 4.31,27.93 ; 8.47,20.9 8.8,21.23 FB4.2 ; 4.31,27.93 3.56,28.68 3.56,32.08 4.17,32.7 4.17,33.02 4.18,33.02 4.18,34.8 7.76,38.38 D9.K 7.84,39.16 7.83,39.17 C56.1 7.83,39.83 7.58,40.08 7.35,40.08 v1(7.02,40.41) ; 4.31,27.93 FB5.2 ; R39.2 14.95,18.63 TP11.1 ; TP11.1 15.55,21.31 15.55,22.09 15.91,22.45 15.91,24.11 16.15,24.35 R28.1 ; TP11.1 15.05,20.6 15.66,20.6 v1(15.76,20.49)
P8_0: length 11.4
  TOP w0.15: U1.H13 v1(11.99,33.88)
  BOTTOM w0.089: J15.7 13.5,42.39 13.9,41.99 13.9,40.87 14.56,40.21 14.56,39.04 14.51,38.99 14.51,38.98 13.14,37.61 13.14,36.32 11.79,34.98 11.79,34.09 11.99,33.89 v1(11.99,33.88)
P8_1: length 12.6
  TOP w0.15: U1.H12 v1(11.99,33.23)
  BOTTOM w0.089: J15.5 13.48,42.79 14.11,42.16 14.11,40.97 14.77,40.31 14.77,38.96 13.38,37.58 13.38,36.28 12.18,35.08 12.18,34.19 12.34,34.02 12.34,33.58 v1(11.99,33.23)
P8_2: length 14.7
  TOP w0.15: U1.H11 v1(11.99,32.58)
  BOTTOM w0.089: J15.3 13.54,43.19 14.31,42.42 14.31,41.07 15,40.39 15,38.91 13.67,37.59 13.67,35.13 14.03,34.77 14.03,34.26 13.85,34.09 12.71,34.09 12.56,33.93 12.56,33.14 v1(11.99,32.58)
P8_3: length 10.9
  TOP w0.15: U1.G13 v1(11.34,33.88)
  BOTTOM w0.089: v1(11.34,33.88) 11.34,34.8 12.86,36.32 12.86,37.6 14.32,39.06 14.32,40.17 13.7,40.79 13.7,41.71 13.42,41.99 J15.9
P8_4: length 11.2
  TOP w0.15: U1.G12 v1(11.34,33.23)
  BOTTOM w0.089: v1(11.34,33.23) 10.96,33.61 10.96,34.7 12.58,36.32 12.58,37.59 14.13,39.14 14.13,40.08 13.5,40.72 13.5,41.43 13.34,41.59 J15.11
P8_5: length 11.4
  TOP w0.15: U1.G11 v1(11.34,32.58)
  BOTTOM w0.089: J15.13 13.18,41.19 13.27,41.1 13.27,40.63 13.92,39.97 13.92,39.21 12.33,37.62 12.33,36.35 10.73,34.75 10.73,33.17 11.32,32.58 v1(11.34,32.58)
P9_0: length 49.7
  TOP w0.15: U1.E11 v1(9.39,32.58)
  L03_SIG1 w0.089: J18.1 30.38,15.51 30.38,21.88 28.87,23.39 28.87,24.78 29.63,25.54 29.63,29.89 29.12,30.39 29.12,30.76 29.58,31.22 29.58,32.48 28.96,33.1 28.96,36.18 28.29,36.86 25.37,36.86 24.45,37.77 15.11,37.77 13.23,35.89 12.73,35.89 10.73,33.88 10.73,32.66 10.21,32.14 9.83,32.14 9.39,32.58 v1(9.39,32.58)
P9_1: length 45.9
  TOP w0.15: U1.E12 v1(9.39,33.23)
  L03_SIG1 w0.089: J18.2 30.62,17.81 30.62,22.94 30.01,23.55 30.01,35.92 28.64,37.28 25.54,37.28 24.67,38.16 14.06,38.16 10.42,34.52 10.16,34.52 9.71,34.08 9.71,33.55 v1(9.39,33.23)
P9_2: length 43.3
  TOP w0.15: U1.E13 9.41,33.86 v1(9.41,34.26)
  L03_SIG1 w0.089: v1(9.41,34.26) 9.92,34.77 10.4,34.77 13.98,38.35 24.78,38.35 25.66,37.47 28.72,37.47 30.21,35.98 30.21,23.65 30.9,22.96 30.9,20.07 J18.3
P9_3: length 41.5
  TOP w0.15: U1.F11 v1(10.04,32.58)
  L03_SIG1 w0.089: v1(10.04,32.58) 10.47,33.01 10.47,34.3 14.14,37.97 24.53,37.97 25.43,37.06 28.36,37.06 29.15,36.26 29.15,33.58 29.29,33.45 29.68,33.45 29.82,33.32 29.82,25.25 29.3,24.73 29.3,23.84 29.75,23.39 v1(29.75,23.04)
  L04_SIG2 w0.089: J18.4 30.47,23.04 v1(29.75,23.04)
P9_4: length 39.8
  TOP w0.15: U1.D13 8.7,33.92 v1(8.7,34.24)
  L03_SIG1 w0.089: v1(8.7,34.24) 8.7,34.59 9.43,35.33 10.42,35.33 13.82,38.73 25.02,38.73 25.12,38.83 25.49,38.83 25.66,38.66 26.14,38.66 26.83,37.97 28.76,37.97 30.59,36.14 30.59,27.99 31.77,26.81 31.77,24.27 J18.5
P9_5: length 38.1
  TOP w0.15: U1.D12 v1(8.74,33.23)
  L03_SIG1 w0.089: v1(31.42,25.73) 31.42,26.58 30.4,27.6 30.4,36.06 28.74,37.72 26.53,37.72 26.13,38.12 25.29,38.12 24.87,38.54 13.9,38.54 10.44,35.08 9.59,35.08 9.05,34.54 9.05,33.88 8.74,33.57 v1(8.74,33.23)
  L04_SIG2 w0.089: v1(31.42,25.73) J18.6
P9_6: length 36.1
  TOP w0.15: U1.D11 v1(8.74,32.58)
  L03_SIG1 w0.089: v1(8.74,32.58) 8.74,32.57 9.41,31.9 10.25,31.9 10.98,32.64 10.98,33.33 11.21,33.55 11.48,33.55 11.67,33.74 11.67,34.23 11.83,34.39 12.77,34.39 13.54,35.16 14.19,35.16 15.32,36.29 15.32,36.77 15.61,37.06 19.22,37.06 19.75,37.58 24.38,37.58 25.33,36.63 28.25,36.63 28.77,36.1 28.77,32.97 29.39,32.36 29.39,31.39 28.89,30.89 v1(28.89,29.71)
  L04_SIG2 w0.089: v1(28.89,29.71) 29.18,29.41 31.71,29.41 J18.7
P9_7: length 33.3
  TOP w0.15: U1.C13 v1(8.09,33.88)
  L03_SIG1 w0.089: J18.8 30.79,32.87 30.79,36.21 28.76,38.24 27.52,38.24 26.42,39.34 25.37,39.34 24.94,38.92 13.74,38.92 10.38,35.56 9.28,35.56 8.32,34.59 8.32,34.1 v1(8.09,33.88)
P10_0_UART_RX: length 18.5
  TOP w0.15: U1.C12 8.12,32.6 6.88,32.6 5.91,33.57 4.63,33.57 4.31,33.25 4.31,30.31 4.05,30.05 4.05,29.21 v1(4.5,28.76)
  L03_SIG1 w0.157: v1(4.5,28.76) 3.76,28.01 3.76,22.8 J17.1
P10_1_UART_TX: length 13.8
  TOP w0.15: v1(4.44,29.56) 4.56,29.68 4.56,33.02 4.77,33.23 5.88,33.23 6.81,32.31 6.95,32.31 7.01,32.25 U1.A11
  L03_SIG1 w0.157: v1(4.44,29.56) 3.23,28.35 3.23,24.81 J17.2
PDM_CLK_P10_4: length 34.5
  TOP w0.15: U1.A10 v1(6.79,31.93)
  L03_SIG1 w0.157: v1(6.79,31.93) 6.33,31.93 5.6,32.66 5.6,35.31 6.5,36.2 6.5,39.01 v1(6.16,39.34)
  L04_SIG2 w0.157: v1(28.65,39.02) 28.35,39.32 26.68,39.32 25.51,38.15 25.21,38.15 25.09,38.27 16.89,38.27 16.37,38.79 6.71,38.79 v1(6.16,39.34)
  BOTTOM w0.15: R72.2 5.72,39.52 5.9,39.34 v1(6.16,39.34) ; v1(28.65,39.02) 28.41,39.26 28.41,39.52 R80.2
PDM_DATA_P10_5: length 33.9
  TOP w0.15: U1.B10 v1(7.44,31.93)
  L03_SIG1 w0.157: v1(6.74,39.37) 6.79,39.31 6.79,36.02 5.88,35.1 5.88,32.77 6.33,32.31 6.95,32.31 6.95,32.31 7.06,32.31 v1(7.44,31.93)
  L04_SIG2 w0.157: v1(6.74,39.37) 7.01,39.09 16.48,39.09 16.99,38.58 24.72,38.58 25.54,39.4 26.39,39.4 26.7,39.7 28.57,39.7 28.95,39.32 v1(29.18,39.32)
  BOTTOM w0.15: v1(29.18,39.32) 28.93,39.57 R79.2 ; R71.2 6.74,39.58 v1(6.74,39.37)
PSEN_INT_P1_4: length 8
  TOP w0.15: U1.H1 11.49,25.57 11.49,25.4 v1(11.46,25.37) ; R66.1 8.01,19.86 v1(8.01,20.39) 8.01,20.4 7.8,20.61 U3.5
  L03_SIG1 w0.157: v1(8.01,20.39) 8.01,20.73 9.53,22.25 9.53,22.62 11.46,24.54 v1(11.46,25.37)
QSPI_CLK_P11_7: length 32
  TOP w0.15: U1.C7 v1(8.09,29.98)
  L04_SIG2 w0.157: v1(8.09,29.98) 9.89,29.98 9.97,29.9 12.46,29.9 13.08,30.52 13.08,31.21 12.68,31.62 12.68,33.14 13.19,33.66 14.74,33.66 15.43,34.34 18.58,34.34 18.83,34.59 21.29,34.59 21.78,35.08 25.19,35.08 25.33,34.95 26.72,34.95 27.01,34.66 27.01,34.02 27.17,33.86 28.38,33.86 28.53,34.02 28.53,34.96 29.13,35.56 29.13,35.95 29.34,36.16 29.64,36.16 29.93,35.86 29.93,34.26 v1(29.49,33.83)
  BOTTOM w0.15: R87.2 v1(29.49,33.83)
QSPI_DATA0_P11_6: length 31.7
  TOP w0.15: U1.B7 v1(7.44,29.98)
  L04_SIG2 w0.089: v1(7.44,29.98) 7.8,29.62 9.28,29.62 9.36,29.54
  L04_SIG2 w0.157: 9.36,29.54 13.37,29.54 13.65,29.83 13.65,30.12 13.34,30.44 13.34,31.37 12.93,31.78 12.93,32.36 13.83,33.25 14.92,33.25 15.6,33.93 18.75,33.93 19.01,34.19 21.5,34.19 22,34.69 25.03,34.69 25.17,34.56 26.23,34.56 26.52,34.27 26.52,33.06 27.02,32.56 28.57,32.56 29,32.99 29,34.88 29.3,35.18 v1(29.51,35.18)
  BOTTOM w0.15: v1(29.51,35.18) 29.27,35.43 R88.2
QSPI_DATA1_P11_5: length 32.1
  TOP w0.15: U1.A7 v1(6.79,29.98)
  L04_SIG2 w0.157: v1(15.12,37.24) 14.7,37.24 14.53,37.06 12.18,37.06 10.42,35.31 7.01,35.31 6.11,34.4 6.11,30.66 v1(6.79,29.98)
  BOTTOM w0.15: v1(15.12,37.24) 15.12,38.3 15.3,38.48 15.3,38.76 15.45,38.91 16.39,38.91 16.52,38.79 16.77,38.79 16.9,38.65 16.9,38.31 17.03,38.18 17.22,38.18 17.35,38.31 17.35,38.65 17.48,38.79 18,38.79 18.14,38.64 18.14,37.59 18,37.44 17.18,37.44 16.75,37.87 15.68,37.87 15.53,37.72 15.53,37.06 15.3,36.83 15.3,36.58 14.92,36.2 14.92,35.21 15.22,34.9 15.22,34.54 14.87,34.19 14.87,33.61 14.97,33.5 15.49,33.5 15.81,33.83 16.27,33.83 16.96,33.14 R89.2
QSPI_DATA2_P11_4: length 21.9
  TOP w0.15: U1.C8 v1(8.09,30.63)
  L04_SIG2 w0.157: v1(16.67,35.66) 16.53,35.52 14.57,35.52 14.22,35.87 13.75,35.87 13.6,35.72 13.6,35.31 14.28,34.62 14.28,34.37 13.98,34.06 13.5,34.06 13.23,34.33 12.23,34.33 12.09,34.47 12.09,34.76 11.95,34.9 11.75,34.9 11.61,34.76 11.61,34.47 11.48,34.33 11.17,34.33 10.4,33.56 10.4,33.3 10.54,33.16 10.89,33.16 11.03,33.02 11.03,32.83 10.89,32.69 10.54,32.69 10.4,32.55 10.4,32.34 10.02,31.96 9.43,31.96 v1(8.09,30.63)
  BOTTOM w0.15: R90.2 17.04,34.4 16.85,34.59 16.52,34.59 16.27,34.34 15.68,34.34 15.55,34.47 15.55,34.76 15.69,34.89 16.21,34.89 16.34,35.02 16.34,35.21 16.21,35.34 15.69,35.34 15.55,35.47 15.55,35.73 15.75,35.93 16.02,35.93 16.29,35.66 v1(16.67,35.66)
QSPI_DATA3_P11_3: length 32.7
  TOP w0.15: U1.B8 v1(7.44,30.63)
  L04_SIG2 w0.157: v1(29.49,33.03) 30.32,33.85 30.32,36.02 29.8,36.54 29.18,36.54 28.74,36.11 28.74,35.72 27.87,34.85 27.37,34.85 26.88,35.33 25.49,35.33 25.28,35.53 21.29,35.53 20.92,35.16 19.94,35.16 19.77,35.33 17.94,35.33 17.1,36.17 16.48,36.17 16.27,35.96 14.67,35.96 14.38,36.26 12.47,36.26 9.94,33.73 8.74,33.73 7.93,32.92 7.93,31.12 v1(7.44,30.63)
  BOTTOM w0.15: R91.2 v1(29.49,33.03)
QSPI_SEL_L_P11_2: length 24.1
  TOP w0.15: U1.A8 v1(6.79,30.63)
  L04_SIG2 w0.157: v1(6.79,30.63) 6.43,30.98 6.43,34.03 6.64,34.23 7.38,34.23 7.84,34.7 10.36,34.7 12.32,36.65 14.77,36.65 v1(14.89,36.78)
  BOTTOM w0.15: v1(14.89,36.78) 14.46,36.35 14.46,34.04 14.13,33.71 12.99,33.71 12.86,33.58 12.86,32.94 12.99,32.82 13.55,32.82 13.75,33.02 15.45,33.02 15.88,33.45 16.11,33.45 16.42,33.15 16.42,32.79 16.58,32.63 16.77,32.63 16.99,32.4 16.99,32.39 R86.2
ROSC_IN_80MHZ: length 2.2
  TOP w0.15: U6.M2 21.45,17.81 21.36,17.81 21.31,17.75 19.66,17.75 R83.2
RSPI_CLK_P12_2: length 11.3
  TOP w0.15: U1.C6 v1(8.09,28.68) ; R292.1 14.36,23.49 14.36,23.71 v1(14.42,23.76)
  L04_SIG2 w0.089: 9.29,27.3 9.25,27.33 9.25,27.53 9.13,27.66 9.13,28.08 9.04,28.17 8.6,28.17 v1(8.09,28.68)
  L04_SIG2 w0.157: v1(14.42,23.76) 14.36,23.82 14.36,24.69 13.98,25.07 11.66,25.07 11.59,24.99 9.76,24.99 9.29,25.47 9.29,27.3
RSPI_CS_P12_3: length 30
  TOP w0.15: R291.1 29.35,22.68 29.65,22.38 v1(29.65,22.12) ; U1.A5 v1(6.79,28.03)
  L04_SIG2 w0.089: v1(6.79,28.03) 6.44,28.38 6.44,29.12 6.73,29.41 8.96,29.41 9.15,29.21 13.9,29.21 14.27,28.84 14.27,28.54 14.46,28.35 14.79,28.35 14.97,28.17 14.97,27.84 15.1,27.71
  L04_SIG2 w0.157: v1(29.65,22.12) 29.05,22.12 27.65,23.52 26.96,23.52 26.45,24.03 21.39,24.03 20.57,24.84 18.58,24.84 18.46,24.96 16.91,24.96 16.09,25.78 16.09,26.37 15.1,27.36 15.1,27.71
RSPI_IRQ_P11_0: length 34
  TOP w0.089: v1(12.41,28.65) 12.41,29.18 11.97,29.62 9.83,29.62 8.72,30.72 8.72,31.07 8.54,31.25 8.07,31.25 U1.B9
  TOP w0.15: U6.C1 27.28,19.63 28.84,19.63 29.04,19.43 v1(29.75,19.43)
  L04_SIG2 w0.089: 14.77,27.1 14.17,27.7 13.36,27.7 v1(12.41,28.65)
  L04_SIG2 w0.157: v1(29.75,19.43) 30.34,20.02 30.34,21.23 29.85,21.72 28.1,21.72 26.76,23.06 21.26,23.06 19.81,24.51 18.48,24.51 18.32,24.66 16.7,24.66 15.73,25.63 15.73,26.14 14.77,27.1
RSPI_MISO_P12_1: length 13.9
  TOP w0.15: U1.B6 v1(7.44,28.68)
  L04_SIG2 w0.089: 14.46,25.07 14.27,25.26 14.27,25.56 14.08,25.75 12.48,25.75 11.44,26.8 10.63,26.8 9.98,27.44 9.98,27.7 8.65,29.03 7.8,29.03 7.45,28.68 v1(7.44,28.68)
  L04_SIG2 w0.157: 14.46,25.07 16.46,23.07 v1(16.46,22.58)
  BOTTOM w0.15: R294.1 16.51,23.44 16.51,22.63 v1(16.46,22.58)
RSPI_MOSI_P12_0: length 15.2
  TOP w0.15: v1(17.7,23.94) 18.04,24.28 R293.1 ; U1.A6 v1(6.79,28.68)
  L04_SIG2 w0.089: 14.36,26.31 14.27,26.4 12.51,26.4 11.86,27.05 10.73,27.05 10.25,27.53 10.25,27.74 8.77,29.22 7.18,29.22 6.79,28.83 v1(6.79,28.68)
  L04_SIG2 w0.157: 14.36,26.31 15,25.68 15,25.4 16.37,24.03 17.61,24.03 v1(17.7,23.94)
RXRES_L_P11_1: length 26.7
  TOP w0.089: U1.C9 8.47,30.9 8.47,30.7 9.81,29.36 11.79,29.36 12.02,29.14 12.02,28.47 v1(12.4,28.09)
  TOP w0.15: R299.1 29.6,21.2 v1(29.65,21.26)
  L04_SIG2 w0.089: 14.36,26.92 14.23,27.05 13.55,27.05 12.51,28.09 v1(12.4,28.09)
  L04_SIG2 w0.157: 14.36,26.92 15.38,25.91 15.38,25.5 16.52,24.36 18.17,24.36 18.32,24.21 19.75,24.21 21.17,22.78 26.43,22.78 27.95,21.26 v1(29.65,21.26)
SDHC_CLK: length 30.9
  TOP w0.15: U1.C5 v1(8.09,28.03)
  L04_SIG2 w0.089: 6.87,26.62 7.3,27.05 7.58,27.05 7.77,27.24 7.77,27.7 v1(8.09,28.03)
  L04_SIG2 w0.157: v1(9.59,36.66) 9.59,36.65 9.48,36.65 9.25,36.42 6,36.42 4.28,34.7 4.28,32.46 3.9,32.08 3.9,30.73 5.72,28.91 5.72,27.25 6.36,26.62 6.87,26.62
  BOTTOM w0.15: v1(9.59,36.66) 10.12,37.19 11.01,37.19 11.82,38 11.82,41.58 10.96,42.44 10.96,43.06 11.28,43.38 11.77,43.38 12.1,43.06 12.1,40.88 12.2,40.79 J15.15
SDHC_CMD: length 30.5
  TOP w0.15: U1.B5 v1(7.44,28.03)
  L04_SIG2 w0.089: 6.61,27.05 6.64,27.02 6.94,27.02 7.12,27.2 7.12,27.7 v1(7.44,28.03)
  L04_SIG2 w0.157: v1(10.12,36.63) 9.64,36.14 6.15,36.14 4.58,34.58 4.58,32.41 4.54,32.36 4.54,32.35 4.19,32.01 4.19,30.95 6,29.14 6,27.54 6.48,27.05 6.61,27.05
  BOTTOM w0.15: J15.17 12.74,40.39 12.25,40.39 12.13,40.26 12.13,37.85 12.02,37.74 12.02,36.45 11.73,36.16 11.55,36.16 11.09,36.62 10.9,36.62 10.77,36.49 10.77,36.3 11.23,35.84 11.23,35.65 10.4,34.82 10.4,33.7 10.25,33.55 10.04,33.55 9.89,33.7 9.89,34.78 10.39,35.27 10.39,36.36 v1(10.12,36.63)
SDHC_DATA00: length 28.8
  TOP w0.089: 6.36,26.26 6.34,26.24
  TOP w0.15: 6.34,26.24 6.34,25.22 6.54,25.02 7.03,25.02 U1.B1 ; v1(5,32.28) 5.88,32.28 6.11,32.05 6.11,31.09 5.62,30.6 5.62,29.52 6.05,29.08 6.05,27.22 6.44,26.84 6.44,26.34 6.36,26.26
  BOTTOM w0.15: J15.18 10.64,40.39 10.91,40.12 10.91,38.53 10.59,38.21 10.2,38.21 10.07,38.34 10.07,38.86 9.94,38.99 9.75,38.99 9.62,38.86 9.62,38.34 9.49,38.21 9.24,38.21 8.11,37.08 8.11,36.5 8.26,36.35 9.2,36.35 9.31,36.25 9.81,36.25 10.04,36.02 10.04,35.33 9.36,34.65 8.29,34.65 7.5,35.43 7.15,35.43 6.18,34.47 5.76,34.47 5.38,34.09 5.38,32.66 v1(5,32.28)
SDHC_DATA01: length 28.7
  TOP w0.15: v1(5,32.84) 5.85,32.84 6.4,32.29 6.4,31.71 6.73,31.38 6.73,31.17 6.05,30.49 6.05,30.2 6.4,29.86 6.4,29.82 6.77,29.46 6.77,29.24 6.4,28.88 6.4,27.23 6.74,26.89 6.96,26.89 U1.A3
  BOTTOM w0.15: v1(5,32.84) 5,34.26 5.64,34.9 6.18,34.9 6.36,35.08 6.36,35.26 6.17,35.45 6.17,35.64 6.31,35.77 6.49,35.77 6.68,35.58 6.86,35.58 7.07,35.79 7.71,35.79 8.52,34.98 9.28,34.98 9.66,35.36 9.66,35.71 9.51,35.86 9.23,35.86 9.08,36.02 8.14,36.02 8,36.16 7.47,36.16 7.36,36.27 7.36,36.43 7.48,36.55 7.6,36.55 7.81,36.75 7.81,37.21 8.54,37.95 8.54,39.21 8.68,39.34 9.15,39.34 9.28,39.47 9.28,39.65 9.15,39.79 8.68,39.79 8.54,39.92 8.54,40.18 9.08,40.72 9.08,41.02 8.8,41.3 8.8,41.53 8.95,41.68 9.28,41.68 9.41,41.55 9.41,40.91 9.53,40.79 J15.16
SDHC_DATA02: length 27.5
  TOP w0.15: U1.B3 v1(7.44,26.73) ; v1(4.51,27.46) 4.51,27.51 3.25,28.76 3.25,30.37 3.46,30.58 3.46,35.15 3.59,35.28 3.59,35.28 5.01,36.71 6.68,36.71 7.59,35.8 9.14,35.8 9.25,35.91 9.25,36.12 9.12,36.25 8.72,36.25 8.52,36.45 v1(8.52,36.83)
  BOTTOM w0.15: v1(8.52,36.83) 8.52,36.88 9.48,37.85 10.73,37.85 11.21,38.33 11.21,40.79 10.82,41.19 J15.14 ; v1(7.44,26.73) 7.22,26.95 6.64,26.95 6.21,27.38 4.96,27.38 4.89,27.46 v1(4.51,27.46)
SDHC_DATA03: length 27.8
  TOP w0.15: U1.B2 v1(7.44,26.08) ; v1(3.21,35.43) 3.21,30.68 3,30.47 3,28.66 3.74,27.92 3.74,27.33 4.13,26.95 v1(4.51,26.95)
  L04_SIG2 w0.157: v1(3.21,35.43) 4.58,35.43 6.49,37.34 8.54,37.34 v1(9.05,36.83)
  BOTTOM w0.15: v1(4.51,26.95) 4.89,26.95 4.99,27.05 6.03,27.05 6.49,26.59 6.93,26.59 v1(7.44,26.08) ; v1(9.05,36.83) 9.74,37.52 10.91,37.52 11.54,38.15 11.54,41.05 11,41.59 J15.12
SDHC_DATA10: length 30.6
  TOP w0.15: U1.C2 v1(8.09,26.08)
  L03_SIG1 w0.089: v1(8.09,26.08) 7.77,25.75 6.43,25.75
  L03_SIG1 w0.157: 6.43,25.75 6.16,26.03 6.16,26.87 5.67,27.36 5.67,29.55 5.66,29.55 5.66,29.85 5.67,29.85 5.67,30.14 6.59,31.06 7.68,31.06 8.09,31.47 8.09,32.37 7.61,32.85 6.64,32.85 6.43,33.06 6.43,34.75 7.81,36.12 7.81,37.21 7.56,37.46 7.56,37.78 7.69,37.91 9.12,37.91 9.25,38.05 9.25,38.25 9.12,38.39 7.69,38.39 7.56,38.52 7.56,38.72 7.69,38.86 9.12,38.86 9.25,39 9.25,39.19 9.12,39.33 7.69,39.33 7.56,39.47 7.56,39.73 8.14,40.31 v1(8.14,40.92)
  BOTTOM w0.15: v1(8.14,40.92) 8.14,41.83 8.29,41.99 J15.10
SDHC_DATA11: length 29.8
  TOP w0.15: v1(5.01,31.71) 5.25,31.95 5.55,31.95 5.78,31.73 5.78,31.11 5.34,30.68 5.34,29.11 5.72,28.73 5.72,27.2 6.16,26.76 6.16,26.43 6.03,26.31 6.03,24.56 6.36,24.23 6.99,24.23 8.2,25.45 8.2,25.54 U1.C1
  L03_SIG1 w0.157: v1(5.01,31.71) 5.25,31.95 5.89,31.95 6.34,31.5 7.6,31.5 7.83,31.72 7.83,32.16 7.4,32.59 6.49,32.59 6.16,32.92 6.16,34.95 7.06,35.85 7.06,37.3 7.22,37.47 7.22,39.9 7.63,40.31 v1(7.63,40.92)
  BOTTOM w0.15: v1(7.63,40.92) 7.63,42.09 7.93,42.39 J15.8
SDHC_DATA12: length 30.4
  TOP w0.15: U1.D3 v1(8.74,26.73)
  L03_SIG1 w0.089: v1(8.74,26.73) 8.42,27.05 7.96,27.05 7.77,26.86 7.77,26.59 7.58,26.4 6.98,26.4 6.82,26.57 ; 7.12,34.23 7.12,33.7 7.27,33.55 7.71,33.55
  L03_SIG1 w0.157: v1(8.65,40.92) 8.65,41.25 8.77,41.38 9.61,41.38 9.76,41.22 9.76,37.55 9.61,37.39 8.47,37.39 8.14,37.06 8.14,35.26 7.12,34.23 ; 6.82,26.57 6.82,26.72 6.11,27.43 6.11,29.16 6.46,29.51 8.19,29.51 8.47,29.79 8.47,31.32 8.35,31.44 8.35,32.91 7.71,33.55
  BOTTOM w0.15: J15.6 7.82,42.79 7.2,42.16 7.2,40.79 7.52,40.47 8.25,40.47 8.65,40.87 v1(8.65,40.92)
SDHC_DATA13: length 29.9
  TOP w0.15: U1.D2 v1(8.74,26.08)
  L03_SIG1 w0.089: 8.74,26.08 7.68,25.02 5.93,25.02
  L03_SIG1 w0.157: 5.93,25.02 5.55,25.4 5.55,26.01 5.37,26.19 5.37,30.27 4.51,31.13 4.51,34.82 5.98,36.3 5.98,37.19 5.72,37.44 5.72,39.01 5.62,39.12 5.62,39.65 5.9,39.93 5.9,40.52 6.04,40.66 6.6,40.66 6.74,40.8 6.74,40.99 6.6,41.13 6.04,41.13 5.9,41.27 5.9,41.46 6.04,41.6 6.6,41.6 6.74,41.74 6.74,41.94 6.6,42.08 6.04,42.08 5.9,42.21 5.9,42.7 6.18,42.98 v1(6.66,42.98) ; 8.74,26.08 v1(8.74,26.08)
  BOTTOM w0.15: v1(6.66,42.98) 7.5,42.98 7.71,43.19 J15.4
SDIO_CLK: length 16.6
  TOP w0.15: v1(25.2,27.2) 26.24,28.25 26.24,29.34 25.92,29.67 24.93,29.67 24.6,30 24.6,30.32 U17.20 ; R54.1 18.75,25.29 v1(19.02,25.55) 19.19,25.55 19.43,25.31 R46.2
  L04_SIG2 w0.157: v1(25.2,27.2) 25.65,26.75 25.65,26.04 25.25,25.63 23.31,25.63 23.17,25.49 23.17,25.03 23.03,24.89 22.83,24.89 22.7,25.03 22.7,25.49 22.56,25.63 22.36,25.63 22.22,25.49 22.22,25.03 22.08,24.89 21.89,24.89 21.75,25.03 21.75,25.49 21.61,25.63 19.09,25.63 v1(19.02,25.55)
SDIO_CMD: length 15.5
  TOP w0.15: U17.22 v1(25.56,31.04) ; R53.1 18.12,29.74 v1(18.37,29.49) 18.63,29.74 R45.2
  L04_SIG2 w0.157: v1(25.56,31.04) 25.29,30.77 24.88,30.77 24.74,30.63 24.74,30.19 24.6,30.05 24.41,30.05 24.27,30.19 24.27,30.63 24.13,30.77 23.94,30.77 23.8,30.63 23.8,30.19 23.66,30.05 23.46,30.05 23.32,30.19 23.32,30.63 23.19,30.77 22.99,30.77 22.85,30.63 22.85,30.19 22.71,30.05 22.52,30.05 22.38,30.19 22.38,30.63 22.24,30.77 21.96,30.77 20.74,29.56 19.47,29.56 18.86,30.18 18.2,30.18 17.62,29.6 17.62,29.2 17.73,29.09 17.95,29.09 18.35,29.49 v1(18.37,29.49)
SDIO_DATA0: length 15.2
  TOP w0.15: U17.24 v1(25.55,31.94) ; R48.1 v1(18.93,26.09) R42.2
  L03_SIG1 w0.157: v1(25.2,26.52) 25.69,27.01 26.19,27.01 26.37,27.19 26.37,30 26.15,30.23 26.15,30.47 26.37,30.7 26.37,31.76 26.18,31.95 25.56,31.95 v1(25.55,31.94)
  L04_SIG2 w0.157: v1(18.93,26.09) 20.37,26.09 20.42,26.04 24.01,26.04 24.5,26.52 v1(25.2,26.52)
SDIO_DATA1: length 16.5
  TOP w0.15: U17.26 v1(25.56,32.84) ; R50.2 18.53,27.64 v1(18.4,27.64) 18.21,27.64 R49.1
  L04_SIG2 w0.157: v1(25.56,32.84) 24.9,32.84 23.94,31.88 23.36,31.88 23.23,32.02 23.23,32.29 23.09,32.43 22.89,32.43 22.75,32.29 22.75,32.02 22.61,31.88 21.41,31.88 20.55,31.01 20.33,31.01 20,30.69 19.54,30.69 18.75,31.47 18.32,31.47 17.44,30.58 17.06,30.58 16.8,30.33 16.8,28.92 18.08,27.64 v1(18.4,27.64)
SDIO_DATA2: length 11.8
  TOP w0.15: U17.23 v1(25.94,31.49) ; R43.2 v1(18.37,28.14) R51.1
  L04_SIG2 w0.157: v1(18.37,28.14) 19.39,29.16 23.3,29.16 23.63,29.49 25.27,29.49 26.16,30.38 26.16,31.27 v1(25.94,31.49)
SDIO_DATA3: length 14.8
  TOP w0.15: U17.25 v1(25.95,32.39) ; R52.1 v1(18.37,28.94) R44.2
  L04_SIG2 w0.157: v1(18.37,28.94) 18.37,28.85 17.98,28.46 17.75,28.46 17.19,29.02 17.19,30.01 17.36,30.18 17.65,30.18 18.04,30.56 18.05,30.56 18.12,30.63 18.98,30.63 19.67,29.94 20.58,29.94 21.94,31.3 24.38,31.3 25.45,32.37 25.76,32.37 25.77,32.38 25.94,32.38 v1(25.95,32.39)
USB_V_SENSE: length 3.4
  BOTTOM w0.15: U2.19 25.65,17.27 25.8,17.12 26.32,17.12 26.99,16.46 R33.2 R36.2
USER_BTN_P5_2: length 16.3
  TOP w0.15: C58.1 20.51,24.43 v1(21.04,24.97) 21.94,24.97 SW2.1 SW2.2 ; U1.M8 v1(14.59,30.63)
  L04_SIG2 w0.157: v1(14.59,30.63) 14.59,29.84 14.95,29.48 14.95,28.65 16.62,26.97 16.62,26.53 16.54,26.45 16.54,25.93 17.18,25.3 18.52,25.3 18.65,25.17 20.84,25.17 v1(21.04,24.97)
USER_LED1_P5_3: length 15
  TOP w0.15: U1.N8 v1(15.24,30.63) ; v1(14.18,19.66) 13.77,19.25 R62.2
  L03_SIG1 w0.157: v1(16.98,26.34) 16.87,26.23 16.87,26.05 16.72,25.9 16.72,25.51 16.11,24.9 16.11,22.75 16.01,22.65 16.01,21.69 14.18,19.86 v1(14.18,19.66)
  L04_SIG2 w0.157: v1(15.24,30.63) 15.24,28.83 16.98,27.09 v1(16.98,26.34)
USER_LED2_P5_4: length 13.6
  TOP w0.15: U1.L9 13.61,30.95 12.89,30.23 12.89,29.62 13.31,29.2 13.31,25.53 13.79,25.05 13.87,25.05 14.03,24.88 14.03,23.05 14.81,22.28 14.81,21.19 14.24,20.62 14.24,20.25 13.8,19.82 13.8,19.76 13.27,19.23 13.27,19.17 R63.2
VBACKUP: length 3.9
  TOP w0.229: U1.D1 v1(8.74,25.43)
  BOTTOM w0.229: R284.2 9.25,23.61 9.66,24.03 9.66,24.67 9.47,24.86 9.24,24.86 C44.1 C43.1 8.4,25.08 v1(8.74,25.43)
VBUCK: length 2.4
  BOTTOM w0.229: R40.1 13.67,21.02 13.67,21.28 13.6,21.34 13.59,21.34 13.43,21.5 13.42,21.5 13.36,21.57 13.36,21.58 13.32,21.61 C35.1 13.28,21.88 13.28,22.24 13.44,22.4 L2.2
VREF: length 1.1
  TOP w0.229: U1.B13 v1(7.44,33.88)
  BOTTOM w0.229: v1(7.44,33.88) 7.57,34 C37.1
VTARG_MEAS: length 2.3
  BOTTOM w0.15: U2.32 20.45,16.52 R31.2 R30.2
WCO_XTAL_IN_P0_0: length 2.5
  TOP w0.15: v1(9.61,27.48) 9.72,27.38 U1.E3
  BOTTOM w0.15: Y1.2 10.3,28.43 10.3,27.71 10.22,27.64 10.22,27.55 10.2,27.53 10.2,27.35 C60.2 9.92,27.48 v1(9.61,27.48)
WCO_XTAL_OUT_P0_1: length 3.7
  TOP w0.15: U1.E2 v1(10.05,26.07)
  BOTTOM w0.15: Y1.1 11.46,28.4 11.46,27.97 11.38,27.88 C61.2 11.31,27.28 10.1,26.07 v1(10.05,26.07)
WL_HOST_WAKE: length 15.9
  TOP w0.15: U17.27 v1(25.95,33.29) ; U1.M7 14.4,29.65 14.72,29.97 15.17,29.97 15.62,30.42 15.62,31.26 v1(16.61,32.25)
  L04_SIG2 w0.157: v1(16.61,32.25) 17.13,32.77 19.75,32.77 20.76,33.78 23.91,33.78 24.29,34.16 25.82,34.16 26.04,33.93 26.04,33.39 v1(25.95,33.29)
WL_REG_ON: length 16.5
  TOP w0.15: U1.M4 14.59,27.38 15.2,27.38 15.71,27.89 15.71,28.32 16.54,29.16 16.54,29.52 17.32,30.29 R47.2 v1(17.32,31.04) ; U17.28 v1(25.57,33.74)
  L04_SIG2 w0.157: v1(17.32,31.04) 17.32,31.84 17.92,32.44 19.69,32.44 20.25,31.88 20.76,31.88 21.7,32.82 23.86,32.82 24.79,33.74 v1(25.57,33.74)
N17065875: length 2.3
  TOP w0.229: U1.J2 v1(12.64,26.08)
  BOTTOM w0.229: v1(12.64,26.08) 13.06,25.65 13.06,24.9 L2.1
N17073640: length 3.8
  TOP w0.15: U1.M2 14.38,26.4 14.72,26.06 15.5,26.06 15.61,25.95 15.71,25.95 17.15,25.95 17.28,26.09 R48.2
N17073643: length 2.9
  TOP w0.15: U1.N2 15.7,26.4 15.71,26.39 15.78,26.31 16.39,26.31 16.82,26.75 16.82,26.85 R49.2
N17073646: length 4.6
  TOP w0.15: U1.L3 v1(13.94,26.73) ; R51.2 16.9,27.72 16.9,27.43 v1(16.21,26.75)
  BOTTOM w0.157: v1(13.94,26.73) 16.2,26.73 v1(16.21,26.75)
N17073649: length 4.4
  TOP w0.15: U1.M3 14.6,26.72 15.65,26.72 16.52,27.6 16.52,28.07 17.32,28.86 R52.2
N17073652: length 4
  TOP w0.15: U1.N3 15.43,27.05 15.71,27.33 16.14,27.77 16.14,28.22 16.92,29 16.92,29.34 R53.2
N17073655: length 3.1
  TOP w0.15: R54.2 17.24,25.29 16.9,25.63 15.05,25.63 14.92,25.75 U1.N1
N17076511: length 15.4
  TOP w0.15: U1.L5 v1(13.94,28.03) ; R56.2 18.55,35.54 18.55,35.81 18.25,36.12 18.25,36.3 17.46,37.08 17.13,37.08 16.8,36.75 16.8,36.56 v1(16.79,36.55)
  L03_SIG1 w0.157: v1(13.94,28.03) 13.94,28.03 14.44,27.53 14.77,27.53 15.38,28.14 15.38,28.98 16.67,30.28 16.67,31.29 17.26,31.88 17.26,32.56 17.1,32.72 17.1,33.99 16.24,34.85 16.24,35.74 16.67,36.17 16.67,36.42 16.79,36.54 v1(16.79,36.55)
N17076512: length 14.2
  TOP w0.15: U1.M5 v1(14.59,28.03) ; R57.2 17.76,37.34 17.02,37.34 16.44,36.75 15.81,36.75 15.76,36.71 v1(15.75,36.71)
  L03_SIG1 w0.157: v1(15.75,36.71) 15.75,34.83 16.8,33.78 16.8,32.59 16.97,32.42 16.97,31.99 16.41,31.44 16.41,30.61 15.02,29.22 15.02,28.45 14.6,28.03 v1(14.59,28.03)
N17076513: length 8.8
  TOP w0.15: U1.L6 v1(13.94,28.68) ; v1(18.14,33.17) 18.38,33.41 R60.2
  L03_SIG1 w0.157: v1(16.04,32.92) 16.25,32.71 16.25,31.95 16.09,31.79 16.09,30.81 13.95,28.68 v1(13.94,28.68)
  L04_SIG2 w0.157: v1(16.04,32.92) 16.56,33.44 17.87,33.44 v1(18.14,33.17)
